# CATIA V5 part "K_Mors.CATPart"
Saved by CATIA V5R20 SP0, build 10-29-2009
Part number: Mors
Bounding box of the stored display mesh (mm): x -950 to -350, y -284.606 to 0, z 82.458 to 219.13
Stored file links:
  G:\Khaled_CFAO_2011\ST2M\ST2M_GR2\jcoetard\Khaled\CAD_CATIA\K_Mors.CATPart
  J:\Thinkmotion\Thinkmotion_COETARD\Maquette_catia\Maquette_catia_R20_Licence_education\jcharlescoetard.CATPRODUCT\Assemblage_Pince_Prehension_Mors_Paralleles.CATProduct
  C:\Program Files\Dassault Systemes\B20\win_b64\startup\materials\French\Catalog.CATMaterial
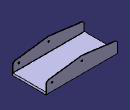
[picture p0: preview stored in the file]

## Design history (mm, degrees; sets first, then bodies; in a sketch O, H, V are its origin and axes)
Set1
  Point1: linked copy from another document
  Plane1 "Plan_Ref": linked copy from another document
  Point2: linked copy from another document
Body1 (main body), material "Aucun"
  Sketch1 on Plane1, origin (0, 0, 0), H (-1, 0, 0), V (0, 0, 1)
    line L1 (350, 82.458) -> (950, 82.458)
    line L2 (950, 82.458) -> (950, 158.049)
    point P3 (950, 180)
    line L3 (350, 82.458) -> (350, 158.049)
    point P4 (350, 180)
    construction line L4 (364, 180) -> (1072, 180)
    axis line L5 (650, 349.8284) -> (650, -7.1716)
    point P9 (650, 82.458)
    line L6 (371.7666, 182.8391) -> (650, 219.1296)
    point P10 (650, 219.1296)
    line L7 (928.2334, 182.8391) -> (650, 219.1296)
    reference projected point E1 (650, 180) from Point1
    reference projected point E2 (650, 180) from Point1
    reference projected point E3 (400, 150) from Point2
    reference projected point E4 (400, 150) from Point2
    arc A1 centre (925, 158.049) radius 25 from (950, 158.049) to (928.2334, 182.8391) ccw
    arc A2 centre (375, 158.049) radius 25 from (350, 158.049) to (371.7666, 182.8391) cw
    distance L3 E3 = 50
    distance L6 E4 = 36.2149
    radius A1 = 25
    radius A2 = 25
    horizontal: L1 H, L4 H
    vertical: L2 V, L3 V, L5 V
    coincidence: L4 P3, P4 L4, P9 L5, P10 L5, L4 E1, L5 E2, L2 P3, L7 P3, L3 P4, L6 P4
    midpoint: P9 L1
    tangency: A1 L2, A1 L7, A2 L3, A2 L6
  Pad1: profile Sketch1, direction (0, -1, 0), length 5
  Sketch2 on Plane1, origin (0, 0, 0), H (-1, 0, 0), V (0, 0, 1)
    line L1 (350, 82.458) -> (600, 82.458)
    line L2 (600, 82.458) -> (600, 92.458)
    line L3 (600, 92.458) -> (700, 92.458)
    line L4 (700, 92.458) -> (700, 82.458)
    point P5 (700, 82.458)
    line L5 (700, 82.458) -> (950, 82.458)
    line L6 (950, 82.458) -> (950, 102.458)
    line L7 (950, 102.458) -> (350, 102.458)
    line L8 (350, 102.458) -> (350, 82.458)
    axis line L9 (650, 340.0344) -> (650, 52.9909)
    point P11 (650, 92.458)
    reference projected point E1 (650, 180) from Point1
    reference projected line E2 (350, 158.049) -> (350, 82.458) from edge [face of Pad1 from Sketch1.L3 | start face of Pad1]
    reference projected line E3 (950, 82.458) -> (950, 158.049) from edge [face of Pad1 from Sketch1.L2 | start face of Pad1]
    reference projected line E4 (300, 82.458) -> (860, 82.458) from edge [face of Pad1 from Sketch1.L1 | start face of Pad1]
    length L6 = 20
    length L4 = 10
    distance L9 L4 = 50
    horizontal: L1 H, L3 H, L5 H, L7 H
    vertical: L2 V, L4 V, L6 V, L8 V, L9 V
    coincidence: P5 L1, P11 L9, L9 E1, L8 E2, L6 E3, L1 E4
    midpoint: P11 L3
  Pad2: profile Sketch2, direction (0, -1, 0), length 279.606
  Sketch3 on face of Pad2, origin (-370, 0, 150), H (1, 0, 0), V (0, 0, -1)
    point P1 (-30, 0)
    reference projected point E1 (-30, 0) from Point2
    coincidence: E1 P1
  Hole1: placed by Sketch3, at (-400, 0, 150) direction (0, -1, 0), diameter 10, depth 10
  Sketch4 on face of Pad2, origin (-620, 0, 180), H (1, 0, 0), V (0, 0, -1)
    point P1 (-30, 0)
    reference projected point E1 (-30, 0) from Point1
    coincidence: E1 P1
  Hole2: placed by Sketch4, at (-650, 0, 180) direction (0, -1, 0), diameter 10, depth 10
  Sketch5 on end face of Pad2, origin (0, -279.606, 0), H (1, 0, 0), V (0, 0, 1)
    line L1 (-950, 82.458) -> (-350, 82.458)
    point P3 (-650, 219.1296)
    axis line L2 (-650, 349.8284) -> (-650, -7.1716)
    construction line L3 (-958.9269, 180) -> (-250.9269, 180)
    point P8 (-950, 180)
    point P9 (-650, 82.458)
    reference projected point E1 (-650, 180) from Point1
    reference projected line E2 (-350, 82.458) -> (-950, 82.458) from edge [end face of Pad1 | face of Pad2]
    reference projected point E3 (-650, 180) from Point1
    line L4 (-650, 219.1296) -> (-371.7666, 182.8391)
    line L5 (-350, 82.458) -> (-350, 158.049)
    reference projected line E4 (-656.4125, 219.966) -> (-378.1791, 183.6755) from edge [end face of Pad1 | face of Pad1 from Sketch1.L6]
    point P10 (-350, 180)
    line L6 (-950, 82.458) -> (-950, 158.049)
    point P11 (-650, 219.1296)
    line L7 (-650, 219.1296) -> (-928.2334, 182.8391)
    point P12 (-950, 180)
    point P13 (-950, 180)
    reference projected line E5 (-921.8209, 183.6755) -> (-643.5875, 219.966) from edge [end face of Pad1 | face of Pad1 from Sketch1.L7]
    arc A1 centre (-925, 158.049) radius 25 from (-950, 158.049) to (-928.2334, 182.8391) cw
    arc A2 centre (-375, 158.049) radius 25 from (-350, 158.049) to (-371.7666, 182.8391) ccw
    radius A1 = 25
    radius A2 = 25
    coincidence: L3 P8, L2 P3, P9 L2, L2 E1, L1 E2, L3 E3, L4 E4, L3 P10, P11 L4, L7 P8, L7 P12, L3 P13, L7 E5, L6 P12, L7 P13, L5 P10, L4 P10, P3 P11
    vertical: L2 V, L5 V, L6 V
    horizontal: L3 H, L1 H
    midpoint: P9 L1
    tangency: A1 L6, A1 L7, A2 L5, A2 L4
  Pad3: profile Sketch5, direction (0, -1, 0), length 5
  Sketch6 on end face of Pad3, origin (-650, -284.606, 170), H (1, 0, 0), V (0, 0, 1)
    point P1 (0, 10)
    reference projected point E1 (0, 10) from Point1
    coincidence: E1 P1
  Hole3: placed by Sketch6, at (-650, -284.606, 180) direction (0, 1, 0), diameter 10, depth 10
  Sketch7 on end face of Pad3, origin (-400, -284.606, 140), H (1, 0, 0), V (0, 0, 1)
    point P1 (0, 10)
    reference projected point E1 (0, 10) from Point2
    coincidence: E1 P1
  Hole4: placed by Sketch7, at (-400, -284.606, 150) direction (0, 1, 0), diameter 10, depth 10
  Fillet1: radius 2, on face of Pad2; end face of Pad1; end face of Pad3; start face of Pad3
